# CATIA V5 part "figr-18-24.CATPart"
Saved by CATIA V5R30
Part number: Part1
Bounding box of the stored display mesh (mm): x 0 to 100, y -127 to 127, z -16 to 0
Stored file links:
  D:\PROJECTS\CATIA V56R 2020\Resources\Parts File\c18_catia_v6_6r2020_prt\figr-18-24.CATPart
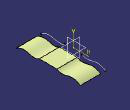
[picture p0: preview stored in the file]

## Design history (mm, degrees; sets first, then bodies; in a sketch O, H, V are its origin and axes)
Body1 (main body)
  Sketch1 on yz-plane, origin (0, 0, 0), H (0, 1, 0), V (0, 0, 1)
    spline S1 through (-127, -16) (-75, -8) (-52.8201, -11.5937) (-35, -5.5937)
    spline S2 through (127, -16) (75, -8) (52.8201, -11.5937) (35, -5.5937)
    point P1 (-35, -5.5937)
    point P2 (35, -5.5937)
    point P3 (-127, -16)
    point P4 (127, -16)
    point P5 (-52.8201, -11.5937)
    point P6 (52.8201, -11.5937)
    point P7 (-75, -8)
    point P8 (75, -8)
    symmetry: S1 S2 V, P1 P2 V, P3 P4 V, P5 P6 V, P7 P8 V
  Extrude1: Element1 Sketch1, Lim1 20, Lim2 -100
  DatumSurface1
